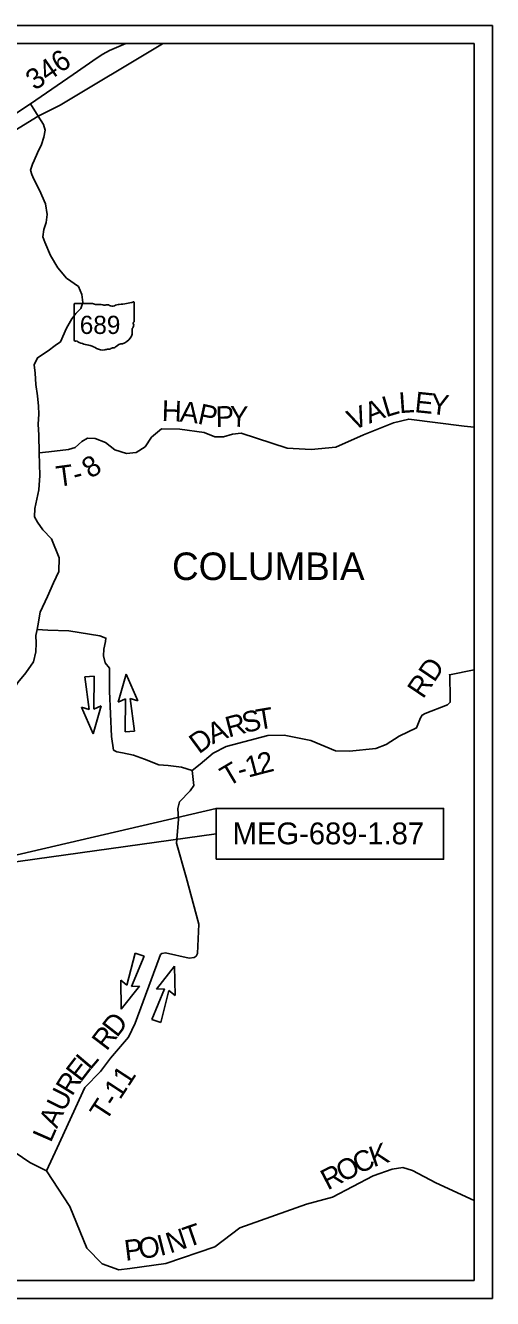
# Model space of a CAD drawing. Extents: x -15 to 405, y -40 to 87.
# Drawn here: x 34.827 to 36.11, y -32.193 to -28.693 of the extents above; entities that cross this region are included whole.
import ezdxf

# ---------------------------------------------------------------- set-up
doc = ezdxf.new("R2010")
doc.units = 0
for name, color, linetype in [('GM_P_State_Location', 7, 'Continuous'), ('GM_P_State_Shield', 7, 'Continuous'), ('GM_X_Adjacent_County', 7, 'Continuous'), ('GM_X_County_Road_Text', 7, 'Continuous'), ('GM_X_Minor_Lake', 7, 'Continuous'), ('GM_X_Minor_River', 7, 'Continuous'), ('GM_X_State_Location', 7, 'Continuous'), ('GM_X_Township', 7, 'Continuous'), ('GM_X_Township_Subdivision', 7, 'Continuous'), ('GM_X_Township_Text', 7, 'Continuous')]:
    doc.layers.add(name, color=color, linetype=linetype)

msp = doc.modelspace()

# ---------------------------------------------------------------- linework, layer by layer
at = {"layer": 'GM_P_State_Location'}
for points in [[(34.8645, -29.8683), (34.8907, -29.8656), (34.945, -29.8591), (34.9636, -29.8534), (34.9818, -29.8374), (34.9974, -29.8283), (35.0186, -29.8291), (35.0471, -29.8397), (35.0722, -29.8598), (35.1045, -29.87), (35.1311, -29.8677), (35.1561, -29.8518), (35.1736, -29.8256), (35.2005, -29.8028), (35.2514, -29.8031), (35.3182, -29.8129), (35.3475, -29.8247), (35.371, -29.8247), (35.3961, -29.8171), (35.4193, -29.8144), (35.5457, -29.8557), (35.6122, -29.8595), (35.6802, -29.8526), (35.7557, -29.8188), (35.8381, -29.786), (35.8803, -29.7758), (36.0322, -29.7954), (36.0603, -29.798)], [(35.2854, -30.7416), (35.3074, -30.7242), (35.3427, -30.6937), (35.378, -30.6755), (35.4927, -30.6458), (35.5375, -30.6446), (35.6112, -30.6594), (35.6792, -30.6875), (35.7172, -30.689), (35.7901, -30.6817), (35.8182, -30.6703), (35.8535, -30.6471), (35.9017, -30.6247), (35.9127, -30.5973), (35.9172, -30.5893), (35.9252, -30.5852), (35.9867, -30.5612), (35.994, -30.5541), (35.9939, -30.5449), (35.9931, -30.4784), (35.9919, -30.4784), (36.0603, -30.4652)]]:
    msp.add_lwpolyline(points, dxfattribs=at)
at = {"layer": 'GM_P_State_Shield'}
msp.add_lwpolyline([(34.8844, -31.8426), (34.9143, -31.7788), (34.9902, -31.6132), (35.0327, -31.5695), (35.0604, -31.5326), (35.1101, -31.4745), (35.1279, -31.4368), (35.1939, -31.2575), (35.1984, -31.248), (35.2015, -31.2446), (35.2117, -31.2435), (35.277, -31.2575), (35.2907, -31.2556), (35.2964, -31.2518), (35.2994, -31.2449), (35.3036, -31.1644), (35.2685, -31.0353), (35.2423, -30.9415), (35.2472, -30.8769), (35.2452, -30.8461), (35.2506, -30.8279), (35.2794, -30.7975), (35.2896, -30.7827), (35.2854, -30.7416), (35.2554, -30.7329), (35.219, -30.7276), (35.1931, -30.7261), (35.1544, -30.7106), (35.124, -30.6992), (35.0932, -30.6935), (35.0784, -30.6909), (35.0685, -30.6856), (35.0632, -30.6483), (35.0574, -30.5241), (35.0578, -30.4607), (35.0457, -30.4458), (35.041, -30.4261), (35.0422, -30.4083), (35.0467, -30.3874), (35.0478, -30.3779), (35.0311, -30.3718), (34.946, -30.3582), (34.8883, -30.3556), (34.8591, -30.3537)], dxfattribs=at)
at = {"layer": 'GM_X_Adjacent_County'}
for points in [[(35.3509, -30.9158), (34.6024, -31.0204), (35.3509, -30.8458)], [(35.3509, -30.9858), (35.9759, -30.9858), (35.9759, -30.8458), (35.3509, -30.8458)]]:
    msp.add_lwpolyline(points, close=True, dxfattribs=at)
at = {"layer": 'GM_X_State_Location'}
for p, q in [((34.9903, -30.4839), (35.016, -30.4823)), ((35.0021, -30.574), (34.9903, -30.4839)), ((35.016, -30.4823), (35.0152, -30.5732)), ((35.0816, -30.5538), (35.104, -30.4768)), ((35.104, -30.4768), (35.1357, -30.5506)), ((35.1017, -30.5448), (35.0816, -30.5538)), ((35.1008, -30.6356), (35.1017, -30.5448)), ((35.1357, -30.5506), (35.1147, -30.5439)), ((35.1147, -30.5439), (35.1266, -30.634)), ((35.0128, -30.6411), (34.9812, -30.5673)), ((34.9812, -30.5673), (35.0021, -30.574)), ((35.0352, -30.5641), (35.0128, -30.6411)), ((35.0152, -30.5732), (35.0352, -30.5641)), ((35.1266, -30.634), (35.1008, -30.6356)), ((35.1056, -31.3318), (35.1284, -31.2438)), ((35.1529, -31.252), (35.118, -31.336)), ((35.1284, -31.2438), (35.1529, -31.252)), ((35.1868, -31.3429), (35.2365, -31.2799)), ((35.2365, -31.2799), (35.2382, -31.3602)), ((35.0903, -31.398), (35.0887, -31.3178)), ((35.0887, -31.3178), (35.1056, -31.3318)), ((35.14, -31.335), (35.0903, -31.398)), ((35.118, -31.336), (35.14, -31.335)), ((35.174, -31.4259), (35.2089, -31.342)), ((35.2089, -31.342), (35.1868, -31.3429)), ((35.2213, -31.3462), (35.1985, -31.4342)), ((35.2382, -31.3602), (35.2213, -31.3462)), ((35.1985, -31.4342), (35.174, -31.4259))]:
    msp.add_line(p, q, dxfattribs=at)
for points in [[(34.8622, -28.9425), (34.9219, -28.913), (35.199, -28.7471), (35.2051, -28.7435)], [(33.92, -29.5325), (34.0264, -29.5191), (34.0966, -29.4981), (34.1523, -29.4696), (34.1966, -29.4361), (34.2789, -29.3665), (34.4569, -29.2094), (34.5266, -29.155), (34.5975, -29.1052), (34.8622, -28.9425)], [(34.8507, -29.0645), (34.8507, -29.0645), (34.8601, -29.0439), (34.8705, -29.0206), (34.8778, -29.0004), (34.881, -28.981), (34.8767, -28.9659), (34.8622, -28.9425)], [(34.8591, -30.3537), (34.861, -30.3442), (34.8674, -30.3062), (34.8877, -30.2634), (34.904, -30.226), (34.9185, -30.1947), (34.9192, -30.1575), (34.8984, -30.1046), (34.875, -30.0798), (34.8595, -30.0595), (34.8518, -30.0447), (34.853, -30.0216), (34.8634, -29.9706), (34.8664, -29.9303), (34.8645, -29.8683), (34.8635, -29.8195), (34.862, -29.7899), (34.864, -29.7625), (34.863, -29.7401), (34.8604, -29.7113), (34.8555, -29.681), (34.8532, -29.6495), (34.851, -29.6264), (34.8599, -29.6069), (34.8893, -29.5883), (34.9089, -29.5737), (34.9232, -29.5629), (34.9394, -29.5259), (34.9539, -29.4999), (34.9652, -29.485), (34.9791, -29.4719), (34.9842, -29.4551), (34.982, -29.4331), (34.9726, -29.4112), (34.9401, -29.3884), (34.9155, -29.3595), (34.8953, -29.3256), (34.8805, -29.2889), (34.8746, -29.2745), (34.877, -29.2548), (34.8836, -29.2353), (34.8868, -29.2129), (34.8823, -29.1841), (34.8659, -29.146), (34.8503, -29.1161), (34.8445, -29.1029), (34.8409, -29.0916), (34.8461, -29.0748), (34.8507, -29.0645)], [(34.6024, -31.0204), (34.6168, -31.0187), (34.6387, -31.012), (34.6584, -31.0015), (34.6704, -30.9903), (34.6785, -30.9735), (34.6791, -30.9546), (34.6829, -30.9257), (34.6932, -30.8944), (34.7067, -30.8479), (34.731, -30.7539), (34.757, -30.64), (34.7704, -30.5882), (34.777, -30.5654), (34.7854, -30.5334), (34.8055, -30.5001), (34.8279, -30.4729), (34.8489, -30.4434), (34.8557, -30.4156), (34.8562, -30.3913), (34.8557, -30.3706), (34.8591, -30.3537)]]:
    msp.add_lwpolyline(points, dxfattribs=at)
at = {"layer": 'GM_X_Township'}
for p, q in [((32.6103, -28.6935), (36.1103, -28.6935)), ((36.1103, -28.6935), (36.1103, -32.1935)), ((32.6603, -28.7435), (36.0603, -28.7435)), ((36.0603, -28.7435), (36.0603, -32.1435)), ((32.6603, -32.1435), (36.0603, -32.1435)), ((32.6103, -32.1935), (36.1103, -32.1935))]:
    msp.add_line(p, q, dxfattribs=at)
at = {"layer": 'GM_X_Township_Subdivision'}
for p, q in [((34.9609, -29.4594), (34.9609, -29.5594)), ((34.9609, -29.5594), (34.9609, -29.4594)), ((34.9609, -29.5594), (34.9609, -29.4594)), ((34.9626, -29.4577), (35.0108, -29.4577)), ((35.1257, -29.4552), (35.1257, -29.5075)), ((35.1257, -29.5075), (35.1257, -29.5075))]:
    msp.add_line(p, q, dxfattribs=at)
for centre, major_axis, start_param, end_param in [((34.9628, -29.4592), (0.00191, 0), 1.712693, 3.28349), ((35.0223, -29.446), (0.0185, 0), 4.042523, 4.731795), ((35.0285, -29.5138), (0.0665, 0), 1.404758, 1.657858), ((35.0436, -29.4586), (0.00534, 0), 3.836095, 5.185415), ((35.0514, -29.4702), (0.0111, 0), 0.950623, 2.079405), ((35.0657, -29.4544), (0.0134, 0), 4.081561, 5.145723), ((35.0893, -29.4882), (0.0352, 0), 1.699011, 2.107814), ((35.067, -29.3212), (0.1748, 0), 4.814394, 5.042369), ((35.1239, -29.455), (0.00183, 0), 6.141152, 7.989035), ((35.0768, -29.5361), (0.0437, 0), 5.101752, 6.440018), ((35.1323, -29.5294), (0.0124, 0), 2.387724, 3.262537), ((35.1253, -29.5114), (0.00284, 0), 1.883978, 3.671073), ((35.1073, -29.518), (0.017, 0), 5.934695, 6.695948), ((35.1238, -29.5077), (0.00196, 0), 5.05454, 6.418171), ((34.9629, -29.5597), (0.00193, 0), 3.00124, 4.508301), ((34.9631, -29.5494), (0.0147, 0), 4.665946, 4.897461), ((34.9662, -29.5652), (0.0053, 0), 0.519207, 1.627899), ((35.0331, -29.4753), (0.1262, 0), 4.195997, 4.488961), ((34.9954, -29.6044), (0.0395, 0), 0.823519, 1.323587), ((35.0953, -29.5875), (0.0239, 0), 1.647645, 2.488434), ((35.0381, -29.5657), (0.0251, 0), 4.026481, 4.996735), ((35.0526, -29.6003), (0.0206, 0), 1.495662, 1.94098), ((35.0545, -29.5732), (0.0133, 0), 4.691044, 5.507374), ((35.0665, -29.5829), (0.00376, 0), 1.147584, 2.315152), ((35.0649, -29.5691), (0.0141, 0), 4.937069, 5.64225)]:
    msp.add_ellipse(centre, major_axis=major_axis, ratio=0.8, start_param=start_param, end_param=end_param, dxfattribs=at)
at = {"layer": 'GM_X_Township_Text'}
for points in [[(34.9577, -28.8279), (35.0237, -28.7823), (35.0396, -28.7721), (35.0582, -28.7627), (35.1023, -28.7435)], [(34.5115, -29.0979), (34.5125, -29.0975), (34.6524, -29.0336), (34.8407, -28.9086), (34.9577, -28.8279)], [(34.8622, -28.9425), (34.8407, -28.9086)], [(34.3296, -31.3917), (34.3583, -31.4004), (34.4175, -31.4248), (34.4692, -31.4458), (34.5083, -31.4591), (34.5341, -31.4793), (34.6801, -31.6429), (34.7199, -31.6867), (34.724, -31.7144), (34.7246, -31.7343), (34.728, -31.7426), (34.7342, -31.749), (34.8393, -31.8198), (34.8844, -31.8426)], [(34.8844, -31.8426), (34.9485, -31.9404), (34.9958, -32.0548), (35.0381, -32.0984), (35.0839, -32.1146), (35.1134, -32.1107)], [(35.1134, -32.1107), (35.1138, -32.1106), (35.2123, -32.0974), (35.3476, -32.0513), (35.4161, -31.999), (35.5993, -31.9337), (35.6704, -31.9152), (35.7825, -31.8561), (35.835, -31.8376), (35.864, -31.8335), (35.8901, -31.8412), (35.955, -31.8755), (36.0603, -31.9242)]]:
    msp.add_lwpolyline(points, dxfattribs=at)

# ---------------------------------------------------------------- texts
at = {"layer": 'GM_X_County_Road_Text'}
msp.add_text('COLUMBIA', height=0.07576, rotation=0, dxfattribs=at).set_placement((35.2297, -30.2182))
at = {"layer": 'GM_X_Minor_Lake'}
for s, height, rotation, p in [('346', 0.05682, 34.5788, (34.8526, -28.8738)), ('K', 0.0568, 18.7126, (35.7831, -31.8329)), ('O', 0.0568, 27.4774, (35.6987, -31.8751)), ('C', 0.0568, 25.3187, (35.7425, -31.8523)), ('R', 0.0568, 27.5513, (35.6573, -31.8966)), ('T', 0.0568, 19.102, (35.2724, -32.0539)), ('O', 0.0568, 8.2383, (35.1414, -32.0852)), ('I', 0.0568, 14.0819, (35.1971, -32.0768)), ('N', 0.0568, 18.3342, (35.2241, -32.0699)), ('P', 0.0568, 6.9685, (35.102, -32.09))]:
    msp.add_text(s, height=height, rotation=rotation, dxfattribs=at).set_placement(p)
at = {"layer": 'GM_X_Minor_River'}
for s, height, rotation, p in [('L', 0.0568, 16.4369, (35.8173, -29.7709)), ('L', 0.0568, 4.0618, (35.8549, -29.7595)), ('E', 0.0568, 354.1014, (35.8946, -29.7564)), ('Y', 0.0568, 353.1425, (35.9367, -29.7608)), ('H', 0.0568, 358.2293, (35.2008, -29.7809)), ('A', 0.0568, 353.414, (35.2495, -29.7823)), ('P', 0.0568, 347.6846, (35.2977, -29.7878)), ('P', 0.0568, 1.5322, (35.3501, -29.7974)), ('Y', 0.0568, 358.7723, (35.3877, -29.7964)), ('V', 0.0568, 22.9345, (35.7263, -29.808)), ('A', 0.0568, 21.3056, (35.7719, -29.7887)), ('8', 0.0568, 33.7197, (35.0061, -29.9409)), ('T', 0.0568, 7.5907, (34.9151, -29.9621)), ('-', 0.0568, 14.0358, (34.9641, -29.9551)), ('RD', 0.05682, 55.8969, (35.9194, -30.547)), ('R', 0.0568, 14.7036, (35.3848, -30.6514)), ('S', 0.0568, 13.8864, (35.4297, -30.6396)), ('T', 0.0568, 9.406, (35.4658, -30.6306)), ('A', 0.0568, 22.9102, (35.3408, -30.6702)), ('D', 0.0568, 36.4109, (35.3036, -30.6981)), ('2', 0.0568, 14.3568, (35.4727, -30.7526)), ('T', 0.0568, 30.647, (35.3838, -30.7878)), ('1', 0.0568, 14.6207, (35.4389, -30.7615)), ('-', 0.0568, 15.5529, (35.4167, -30.7677)), ('D', 0.0568, 51.992, (35.0781, -31.4781)), ('R', 0.0568, 52.7061, (35.0499, -31.5151)), ('E', 0.0568, 52.4473, (34.9788, -31.601)), ('L', 0.0568, 49.6727, (35.0042, -31.5678)), ('T-11', 0.05682, 56.8677, (35.0476, -31.7088)), ('R', 0.0568, 57.9966, (34.9549, -31.6394)), ('U', 0.0568, 63.5458, (34.9333, -31.6828)), ('A', 0.0568, 66.3204, (34.9135, -31.728)), ('L', 0.0568, 66.3204, (34.8965, -31.7669))]:
    msp.add_text(s, height=height, rotation=rotation, dxfattribs=at).set_placement(p)
at = {"layer": 'GM_X_Township'}
msp.add_text('MEG-689-1.87', height=0.06, dxfattribs=at).set_placement((35.3961, -30.9447))
at = {"layer": 'GM_X_Township_Subdivision'}
msp.add_text('689', height=0.05, dxfattribs=at).set_placement((34.9761, -29.5416))

doc.saveas('drawing.dxf')
